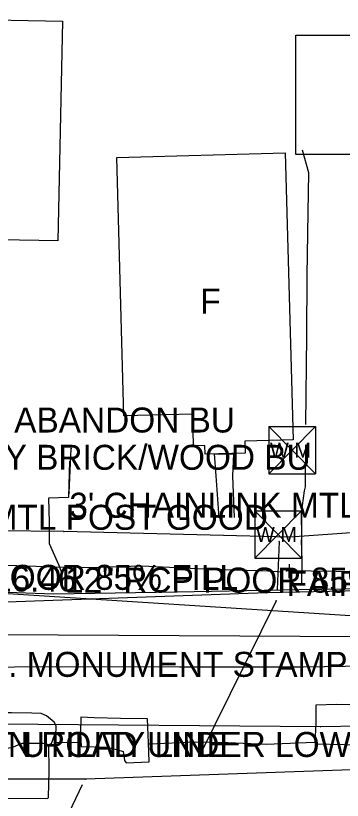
# Model space of a CAD drawing. Extents: x 1304270 to 1306561, y 1876019 to 1876752.
# Drawn here: x 1305527.1 to 1305592.5, y 1876380.2 to 1876537.2 of the extents above; entities that cross this region are included whole.
import ezdxf

# ---------------------------------------------------------------- set-up
doc = ezdxf.new("R2010")
doc.units = 0
for name, color, linetype in [('Default', 7, 'Continuous'), ('S_BUILDING', 7, 'Continuous'), ('S_BUILDING_ANNOT', 7, 'Continuous'), ('S_DITCHLINE', 7, 'Continuous'), ('S_DRG_PT_SYM', 7, 'Continuous'), ('S_DRIVEWAY', 7, 'Continuous'), ('S_EDGE_CONCRETE', 7, 'Continuous'), ('S_EDGE_PAVEMENT', 7, 'Continuous'), ('S_ELECTRIC_UTILITIES_ANNOT', 7, 'Continuous'), ('S_FENCE', 7, 'Continuous'), ('S_FENCE_ANNOT', 7, 'Continuous'), ('S_FIBER_OPTIC_CABLE', 7, 'Continuous'), ('S_GAS_UTILITIES', 7, 'Continuous'), ('S_HEADWALL', 7, 'Continuous'), ('S_MSC_PT_SYM', 7, 'Continuous'), ('S_PARKING', 7, 'Continuous'), ('S_PAVEMENT_CROWN', 7, 'Continuous'), ('S_PRIMARY_CTL_ANNOT', 7, 'Continuous'), ('S_SANITARY_SEWER', 7, 'Continuous'), ('S_SHOULDER', 7, 'Continuous'), ('S_SIDE_DRAIN', 7, 'Continuous'), ('S_SIDE_DRAIN_ANNOT', 7, 'Continuous'), ('S_SIDEWALK', 7, 'Continuous'), ('S_SURVEY_TEXT_ANNOT', 7, 'Continuous'), ('S_UTL_PT_SYM', 7, 'Continuous'), ('S_WATER_UTILITIES', 7, 'Continuous')]:
    doc.layers.add(name, color=color, linetype=linetype)

msp = doc.modelspace()

# ---------------------------------------------------------------- linework, layer by layer
at = {"layer": 'Default'}
msp.add_line((1305473.53, 1876424.94), (1305993.25, 1876391.55), dxfattribs=at)
at = {"layer": 'S_BUILDING'}
for points in [[(1305479.97, 1876457.85), (1305481.58, 1876537.18), (1305536.46, 1876536.07), (1305535.57, 1876492.14), (1305524.09, 1876492.37), (1305523.36, 1876456.62), (1305509.6, 1876456.9), (1305509.49, 1876451.36), (1305496.42, 1876451.63), (1305496.54, 1876457.52)], [(1305583.2, 1876509.43), (1305583.21, 1876533.31), (1305603.68, 1876533.3), (1305603.67, 1876509.42)], [(1305548.77, 1876457.13), (1305547.38, 1876508.81), (1305581.11, 1876509.72), (1305582.66, 1876452.37), (1305573.02, 1876452.11), (1305573.09, 1876449.69), (1305565.03, 1876449.47), (1305564.99, 1876451.19), (1305562.75, 1876451.13), (1305562.58, 1876457.5)]]:
    msp.add_lwpolyline(points, close=True, dxfattribs=at)
at = {"layer": 'S_DITCHLINE'}
msp.add_lwpolyline([(1305537.04, 1876427.04), (1305541.47, 1876426.83), (1305552.41, 1876427.17), (1305564.82, 1876426.57), (1305577.58, 1876426.17), (1305580.66, 1876425.93)], dxfattribs=at)
at = {"layer": 'S_DRG_PT_SYM'}
for points in [[(1305537.01, 1876426.79), (1305537.01, 1876426.84), (1305537.01, 1876426.79), (1305536.96, 1876426.79), (1305537.01, 1876426.79), (1305537.01, 1876426.74), (1305537.01, 1876426.79), (1305537.06, 1876426.79)], [(1305581.35, 1876426.14), (1305581.35, 1876426.19), (1305581.35, 1876426.14), (1305581.3, 1876426.14), (1305581.35, 1876426.14), (1305581.35, 1876426.09), (1305581.35, 1876426.14), (1305581.4, 1876426.14)]]:
    msp.add_lwpolyline(points, dxfattribs=at)
at = {"layer": 'S_DRIVEWAY'}
for points in [[(1305585.23, 1876455.39), (1305585.43, 1876473.17), (1305585.51, 1876485.22), (1305585.66, 1876497.83), (1305585.8, 1876505.78), (1305584.53, 1876510.27)], [(1305585.18, 1876451.37), (1305585.07, 1876442.96), (1305584.91, 1876442.16), (1305584.28, 1876437.76), (1305584.38, 1876432.86)], [(1305537.88, 1876448.1), (1305537.71, 1876440.8), (1305533.69, 1876440.69), (1305533.82, 1876435.82), (1305533.83, 1876431.61), (1305535.66, 1876427.39), (1305536.31, 1876425.89)], [(1305584.41, 1876423.28), (1305584.45, 1876428.1), (1305584.34, 1876432.38)]]:
    msp.add_lwpolyline(points, dxfattribs=at)
at = {"layer": 'S_EDGE_CONCRETE'}
for points in [[(1305587.07, 1876391.56), (1305592.92, 1876391.39), (1305600.11, 1876391.1), (1305599.86, 1876394.71), (1305599.63, 1876399.29), (1305591.28, 1876399.4), (1305587.25, 1876399.27), (1305587.19, 1876395.57), (1305587.04, 1876391.81)], [(1305587.04, 1876391.81), (1305587.07, 1876391.56)]]:
    msp.add_lwpolyline(points, dxfattribs=at)
for points in [[(1305517.87, 1876390.42), (1305520.39, 1876390.41), (1305523.12, 1876390.49), (1305526.37, 1876390.81), (1305528.41, 1876391.65), (1305532.63, 1876391.7), (1305533.75, 1876391.41), (1305534.32, 1876391.63), (1305535.21, 1876394.24), (1305535.21, 1876395.11), (1305534.83, 1876395.88), (1305533.28, 1876397.16), (1305532.25, 1876397.62), (1305530.37, 1876397.69), (1305526.25, 1876397.73), (1305523.02, 1876397.76), (1305517.97, 1876397.98), (1305517.88, 1876394.59)], [(1305540.24, 1876391), (1305545.46, 1876390.88), (1305547.6, 1876390.36), (1305548.67, 1876389.98), (1305548.88, 1876388.2), (1305549.24, 1876387.72), (1305553.86, 1876387.93), (1305553.7, 1876391.77), (1305553.52, 1876396.54), (1305548.11, 1876396.62), (1305542.85, 1876396.77), (1305540.18, 1876396.87), (1305540.11, 1876393.67)]]:
    msp.add_lwpolyline(points, close=True, dxfattribs=at)
at = {"layer": 'S_EDGE_PAVEMENT'}
for points in [[(1305388.38, 1876420.94), (1305412.9, 1876420.99), (1305437.42, 1876421.04), (1305451.62, 1876420.93), (1305465.15, 1876420.97), (1305478.67, 1876421.01), (1305492.19, 1876421.05), (1305505.71, 1876421.09), (1305520.11, 1876421.2), (1305523.54, 1876421.95), (1305534.76, 1876421.53), (1305559.32, 1876421.96), (1305583.88, 1876422.38), (1305606.66, 1876422.73)], [(1305534.88, 1876391.78), (1305539.91, 1876391.87)], [(1305553.84, 1876391.52), (1305563.13, 1876391.93), (1305569.6, 1876391.79), (1305577.25, 1876391.49), (1305586.86, 1876391.86)]]:
    msp.add_lwpolyline(points, dxfattribs=at)
at = {"layer": 'S_FENCE'}
msp.add_line((1305537.86, 1876441.76), (1305538.21, 1876450.6), dxfattribs=at)
msp.add_lwpolyline([(1305537.86, 1876441.76), (1305538.21, 1876450.6)], dxfattribs=at)
msp.add_lwpolyline([(1305537.86, 1876441.76), (1305538.21, 1876450.6)], dxfattribs=at)
at = {"layer": 'S_FIBER_OPTIC_CABLE'}
for p, q in [((1305605.99, 1876434.57), (1305581.98, 1876432.88)), ((1305536.77, 1876434.03), (1305507.97, 1876434.21)), ((1305581.98, 1876432.88), (1305536.77, 1876434.03)), ((1305588.12, 1876394.97), (1305508.02, 1876395.58)), ((1305633.63, 1876395.59), (1305588.12, 1876394.97))]:
    msp.add_line(p, q, dxfattribs=at)
at = {"layer": 'S_GAS_UTILITIES'}
for p, q in [((1305599.74, 1876386.5), (1305541.16, 1876384.5)), ((1305541.16, 1876384.5), (1305484.25, 1876384.34))]:
    msp.add_line(p, q, dxfattribs=at)
at = {"layer": 'S_HEADWALL'}
msp.add_lwpolyline([(1305581.85, 1876427.5), (1305581.8, 1876424.65)], dxfattribs=at)
at = {"layer": 'S_MSC_PT_SYM'}
for points in [[(1305538.21, 1876450.6), (1305538.21, 1876450.65), (1305538.21, 1876450.6), (1305538.16, 1876450.6), (1305538.21, 1876450.6), (1305538.21, 1876450.55), (1305538.21, 1876450.6), (1305538.26, 1876450.6)], [(1305537.86, 1876441.76), (1305537.86, 1876441.81), (1305537.86, 1876441.76), (1305537.81, 1876441.76), (1305537.86, 1876441.76), (1305537.86, 1876441.71), (1305537.86, 1876441.76), (1305537.91, 1876441.76)]]:
    msp.add_lwpolyline(points, dxfattribs=at)
at = {"layer": 'S_PARKING'}
msp.add_lwpolyline([(1305533.16, 1876359.56), (1305534.16, 1876370.45), (1305537.81, 1876377.8), (1305540.53, 1876383.43)], dxfattribs=at)
at = {"layer": 'S_PAVEMENT_CROWN'}
msp.add_lwpolyline([(1305413.65, 1876406.71), (1305437.28, 1876406.8), (1305461.2, 1876406.7), (1305485.13, 1876406.59), (1305486.04, 1876406.61), (1305510.54, 1876406.81), (1305535.03, 1876407.01), (1305559.9, 1876406.97), (1305584.78, 1876406.94), (1305605.66, 1876407.25)], dxfattribs=at)
at = {"layer": 'S_SANITARY_SEWER'}
msp.add_line((1305626.32, 1876412.77), (1305348.54, 1876414.26), dxfattribs=at)
at = {"layer": 'S_SHOULDER'}
msp.add_lwpolyline([(1305437.27, 1876380.42), (1305446.39, 1876380.5), (1305453.47, 1876380.78), (1305472.77, 1876380.64), (1305486.07, 1876380.72), (1305499.38, 1876380.8), (1305512.87, 1876380.68), (1305533.51, 1876380.58), (1305533.72, 1876380.81), (1305533.8, 1876386.24), (1305533.75, 1876391.26)], dxfattribs=at)
at = {"layer": 'S_SIDE_DRAIN'}
for p, q in [((1305537.01, 1876426.79), (1305521.46, 1876427.34)), ((1305597.54, 1876425.9), (1305581.35, 1876426.14))]:
    msp.add_line(p, q, dxfattribs=at)
at = {"layer": 'S_SIDEWALK'}
msp.add_lwpolyline([(1305567.85, 1876436.72), (1305567.25, 1876445.14), (1305566.93, 1876449.55), (1305570.7, 1876449.54), (1305570.53, 1876445.06), (1305570.89, 1876436.84)], dxfattribs=at)
at = {"layer": 'S_UTL_PT_SYM'}
for points in [[(1305536.77, 1876434.03), (1305536.77, 1876434.08), (1305536.77, 1876434.03), (1305536.72, 1876434.03), (1305536.77, 1876434.03), (1305536.77, 1876433.98), (1305536.77, 1876434.03), (1305536.82, 1876434.03)], [(1305581.98, 1876432.88), (1305581.98, 1876432.93), (1305581.98, 1876432.88), (1305581.93, 1876432.88), (1305581.98, 1876432.88), (1305581.98, 1876432.83), (1305581.98, 1876432.88), (1305582.03, 1876432.88)], [(1305579.88, 1876431.99), (1305579.88, 1876432.04), (1305579.88, 1876431.99), (1305579.83, 1876431.99), (1305579.88, 1876431.99), (1305579.88, 1876431.94), (1305579.88, 1876431.99), (1305579.93, 1876431.99)], [(1305577.4, 1876421.77), (1305577.4, 1876421.82), (1305577.4, 1876421.77), (1305577.35, 1876421.77), (1305577.4, 1876421.77), (1305577.4, 1876421.72), (1305577.4, 1876421.77), (1305577.45, 1876421.77)], [(1305579.45, 1876422.39), (1305579.45, 1876422.44), (1305579.45, 1876422.39), (1305579.4, 1876422.39), (1305579.45, 1876422.39), (1305579.45, 1876422.34), (1305579.45, 1876422.39), (1305579.5, 1876422.39)], [(1305579.29, 1876420.14), (1305579.29, 1876420.19), (1305579.29, 1876420.14), (1305579.24, 1876420.14), (1305579.29, 1876420.14), (1305579.29, 1876420.09), (1305579.29, 1876420.14), (1305579.34, 1876420.14)], [(1305588.12, 1876394.97), (1305588.12, 1876395.02), (1305588.12, 1876394.97), (1305588.07, 1876394.97), (1305588.12, 1876394.97), (1305588.12, 1876394.92), (1305588.12, 1876394.97), (1305588.17, 1876394.97)], [(1305563.91, 1876389.13), (1305563.91, 1876389.18), (1305563.91, 1876389.13), (1305563.86, 1876389.13), (1305563.91, 1876389.13), (1305563.91, 1876389.08), (1305563.91, 1876389.13), (1305563.96, 1876389.13)], [(1305541.16, 1876384.5), (1305541.16, 1876384.55), (1305541.16, 1876384.5), (1305541.11, 1876384.5), (1305541.16, 1876384.5), (1305541.16, 1876384.45), (1305541.16, 1876384.5), (1305541.21, 1876384.5)]]:
    msp.add_lwpolyline(points, dxfattribs=at)
at = {"layer": 'S_WATER_UTILITIES'}
for p, q in [((1305577.82, 1876455.02), (1305587.16, 1876455.02)), ((1305577.82, 1876455.02), (1305577.82, 1876445.52)), ((1305577.82, 1876455.02), (1305587.16, 1876445.52)), ((1305587.16, 1876455.02), (1305577.82, 1876445.52)), ((1305587.16, 1876455.02), (1305587.16, 1876445.52)), ((1305577.82, 1876445.52), (1305587.16, 1876445.52)), ((1305575.01, 1876438.17), (1305584.35, 1876438.17)), ((1305575.01, 1876438.17), (1305575.01, 1876428.68)), ((1305575.01, 1876438.17), (1305584.35, 1876428.68)), ((1305584.35, 1876438.17), (1305575.01, 1876428.68)), ((1305584.35, 1876438.17), (1305584.35, 1876428.68)), ((1305579.88, 1876431.99), (1305579.45, 1876422.39)), ((1305575.01, 1876428.68), (1305584.35, 1876428.68)), ((1305577.4, 1876421.77), (1305484.91, 1876418.45)), ((1305609.14, 1876422.38), (1305577.4, 1876421.77)), ((1305579.29, 1876420.14), (1305563.91, 1876389.13))]:
    msp.add_line(p, q, dxfattribs=at)

# ---------------------------------------------------------------- texts
at = {"layer": 'S_BUILDING_ANNOT'}
msp.add_text('F', height=5, dxfattribs=at).set_placement((1305564.08, 1876477.61))
at = {"layer": 'S_ELECTRIC_UTILITIES_ANNOT'}
msp.add_text('POINT ON ROAD UNDER LOW L', height=5, dxfattribs=at).set_placement((1305498.07, 1876388.92))
at = {"layer": 'S_FENCE_ANNOT'}
for s, p in [("3' CHAINLINK MTL POST GOOD", (1305537.86, 1876436.76)), ('4" CHAINLINK MTL POST GOOD', (1305476.42, 1876434.35))]:
    msp.add_text(s, height=5, dxfattribs=at).set_placement(p)
at = {"layer": 'S_PRIMARY_CTL_ANNOT'}
msp.add_text('PD:AHTD STD. MONUMENT STAMPED PN:2', height=5, dxfattribs=at).set_placement((1305481.03, 1876404.94))
at = {"layer": 'S_SIDE_DRAIN_ANNOT'}
for s, p in [('12" RCP 45% 16.46', (1305479.68, 1876422.01)), ('POOR 85% FILL', (1305521.46, 1876422.34)), ('12" RCP POOR 85% FILL 15.56', (1305537.01, 1876421.79)), ('FAIR 60% FILL', (1305581.35, 1876421.14))]:
    msp.add_text(s, height=5, dxfattribs=at).set_placement(p)
at = {"layer": 'S_SURVEY_TEXT_ANNOT'}
for s, p in [('1STRY WOOD/BRICK ABANDON BU', (1305457.72, 1876453.81)), ('1STRY BRICK/WOOD BU', (1305507.8, 1876446.35)), ('LOWEST UTILITY LINE', (1305498.07, 1876388.92))]:
    msp.add_text(s, height=5, dxfattribs=at).set_placement(p)
at = {"layer": 'S_WATER_UTILITIES'}
for p in [(1305578.03, 1876448.78), (1305575.22, 1876431.94)]:
    msp.add_text('W M', height=3, rotation=360, dxfattribs=at).set_placement(p)

doc.saveas('drawing.dxf')
